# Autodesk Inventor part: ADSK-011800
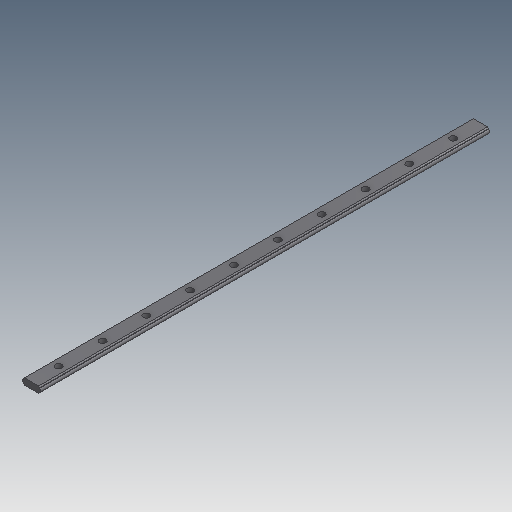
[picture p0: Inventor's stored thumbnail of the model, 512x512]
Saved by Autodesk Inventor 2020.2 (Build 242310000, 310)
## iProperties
Created: 1999-12
Part Number: ADSK-011800
Material: Acier (alliage faible hypertrempé)
Document SubType Name: Modeling
Designer: sspink
Density: 7.84 g/cm^3
Appearance: Metal-Steel(Polish)
Mass: 8209.83 g
Surface Area: 1705.93 cm^2
Volume: 1047.17 cm^3
Control State: 0
Master: False
Checked Out: False
Shininess: 0.0
Length Units: 11269
Angle Units: 11279
Time Units: 11290
Mass Units: 11283
Length Display Precision: 3
Angle Display Precision: 2
Compacted: True
Dimensions: 18x1280x52 mm
Mass: 8,21 kg
VLT_Material: Acier (alliage faible hypertrempé)
Density: 0.0
Volumn: 0.0
Area: 0.0
PropertySet Name: Model Information
Author: sspink
Revision Number: -
Title: ADSK-011800
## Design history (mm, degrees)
node "Extrusion1" dims "d22" = 1280, "d23" = 0
node "Hole1" dims "d28" = 11, "d29" = 19, "d30" = 13, "d31" = 60 deg, "d32" = 8, "d33" = 118 deg
node "Solide1"
node "Corps solides"
node "Corps surfaciques"
sketch "Sketch1"
  geometry: L1 (0, 9)-(0, -25); L2 (-21, -5)-(-21, 5); L3 (-23, 6.083)-(-20.083, 9); L4 (-20.083, 9)-(0, 9); L5 (0, 9)-(20.083, 9); L6 (20.083, 9)-(23, 6.083); L7 (21, 5)-(21, -5); L8 (21, -5)-(20.778, -5); L9 (-23, -6.083)-(-23, -4.583); L10 (-23, 6.083)-(-23, 4.583); L11 (23, 4.583)-(23, 6.083); L12 (23, -4.583)-(23, -6.083); L13 (-23, -6.083)-(-20.083, -9); L14 (-20.083, -9)-(20.083, -9); L15 (20.083, -9)-(23, -6.083); L16 (-21, 0)-(21, 0); A1 r 5 centre (-21, 0) between (-23, -4.583) and (-23, 4.583); A2 r 5 centre (21, 0) between (23, 4.583) and (23, -4.583); 1 further point
  constraints: 32 end point, 6 equal length, 4 parallel, 4 point on circle, 3 collinear, 3 midpoint, 3 perpendicular, 2 centre point, 1 equal radius, 1 point on line, 1 vertical
  dimensions: "d0" = 34 distance of L1.start L1.end; "d1" = 42 distance between parallel lines of L7 L2; "d2" = 10 diameter of A1; "d4" = 10 distance of L2.start L2.end; "d7" = 23 distance between parallel lines of L11 L1; "d8" = 23 distance between parallel lines of L1 L9; "d9" = 23 distance between parallel lines of L10 L1; "d10" = 23 distance between parallel lines of L12 L1; "d11" = 1.5 distance of L3.start L10.end; "d12" = 1.5 distance of L9.start L9.end (= d11); "d34" = 18 distance between parallel lines of L14 L4; "d35" = 9 distance between parallel lines of L14 L16 (= 0.5 x d34); "d36" = 42 distance of L16.end L16.start
sketch "Sketch2"
  geometry: L1 (0, -1280)-(40.165, -1280) reference; L2 (40.165, 0)-(0, 0) reference; 12 further points
  constraints: 2 midpoint, 13 other
  dimensions: "d37" = 77.5 distance from line of point (20.083, -1202.5) L1; "d43" = 125 distance of point (20.083, -327.5) point (20.083, -452.5); "d44" = 125 distance of point (20.083, -77.5) point (20.083, -202.5); "d47" = 125 distance of point (20.083, -1077.5) point (20.083, -1202.5); "d48" = 125 distance of point (20.083, -952.5) point (20.083, -1077.5); "d49" = 125 distance of point (20.083, -827.5) point (20.083, -952.5); "d50" = 125 distance of point (20.083, -702.5) point (20.083, -827.5); "d51" = 125 distance of point (20.083, -702.5) point (20.083, -577.5); "d52" = 125 distance of point (20.083, -577.5) point (20.083, -452.5); "d53" = 125 distance of point (20.083, -202.5) point (20.083, -327.5)
